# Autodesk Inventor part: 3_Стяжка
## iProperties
Created: 2009-12
Part Number: 3_Стяжка
Document SubType Name: Modeling
Designer: Jeck
Density: 1 g/cm^3
Author: Jeck
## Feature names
1. Выдавливание1 [Extrusion]
2. Выдавливание2 [Extrusion]
3. Выдавливание3 [Extrusion]
4. Фаска1 [Chamfer]
5. Зеркальное отражение1 [Mirror]
